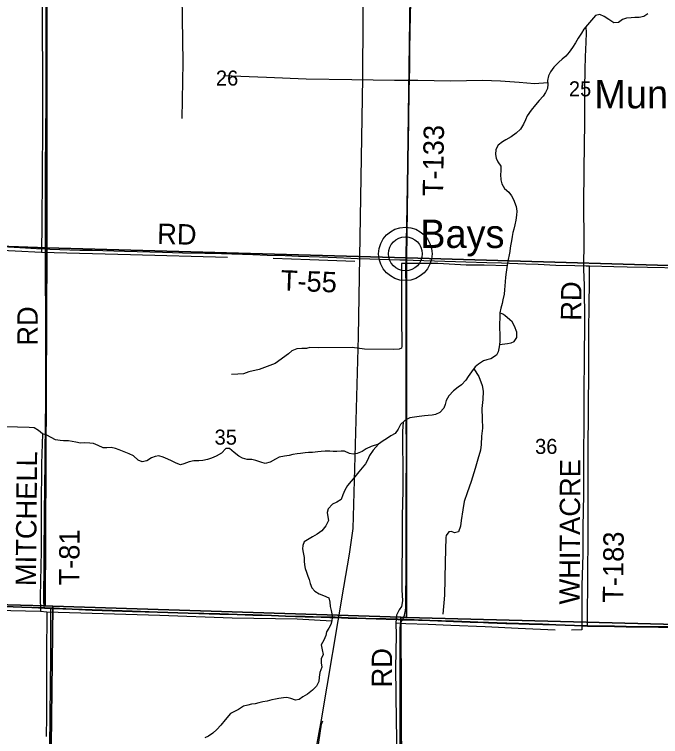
# Model space of a CAD drawing. Extents: x 0 to 39.4, y 0 to 22.
# Drawn here: x 3.277 to 5.077, y 15.083 to 17.096 of the extents above; entities that cross this region are included whole.
import ezdxf

# ---------------------------------------------------------------- set-up
doc = ezdxf.new("R2010")
doc.units = 0
for name, color, linetype in [('GM_X_Interstate_Route', 7, 'Continuous'), ('GM_X_Minor_River', 7, 'Continuous'), ('GM_X_Rail_Line', 7, 'Continuous'), ('GM_X_Section', 7, 'Continuous'), ('GM_X_Section_Text', 7, 'Continuous'), ('GM_X_Township_Road', 7, 'Continuous'), ('GM_X_Township_Road_Text', 7, 'Continuous'), ('GM_X_Unincorporated', 7, 'Continuous'), ('GM_X_Unincorporated_Location', 7, 'Continuous'), ('GM_X_Unincorporated_Text', 7, 'Continuous')]:
    doc.layers.add(name, color=color, linetype=linetype)

msp = doc.modelspace()

# ---------------------------------------------------------------- linework, layer by layer
at = {"layer": 'GM_X_Interstate_Route'}
for points in [[(3.2233, 15.4465), (3.2979, 15.4439), (3.3258, 15.4428), (3.36, 15.4417), (3.3603, 15.4416), (3.378, 15.4408), (3.3848, 15.4405), (3.4376, 15.4384), (3.4935, 15.4361), (3.6053, 15.4322), (3.6752, 15.43), (3.7607, 15.4272), (3.8492, 15.4246), (3.8974, 15.4233), (3.9409, 15.4219), (3.9937, 15.4204), (4.0325, 15.4189), (4.0869, 15.4172), (4.132, 15.4161), (4.1553, 15.4158), (4.1708, 15.4154), (4.1879, 15.4145), (4.2065, 15.4136), (4.2562, 15.4122), (4.3121, 15.4108), (4.3277, 15.4105), (4.3452, 15.4097), (4.358, 15.4092), (4.3696, 15.4088), (4.4348, 15.4066), (4.5, 15.4043), (4.5466, 15.4026), (4.5684, 15.402), (4.5979, 15.4009), (4.646, 15.399), (4.6491, 15.399), (4.6678, 15.3983), (4.6818, 15.398), (4.7113, 15.3969), (4.7486, 15.396), (4.7858, 15.3946), (4.8371, 15.3927), (4.8588, 15.3919), (4.8733, 15.3915), (4.8992, 15.3909), (4.9116, 15.3907), (4.9489, 15.3902), (4.9816, 15.3896), (5.0033, 15.3891), (5.0344, 15.3891), (5.0717, 15.3886), (5.1012, 15.3883)], [(5.1012, 15.3883), (5.0717, 15.3886), (5.0344, 15.3891), (5.0033, 15.3891), (4.9816, 15.3896), (4.9489, 15.3902), (4.9116, 15.3907), (4.8992, 15.3909), (4.8733, 15.3915), (4.8588, 15.3919), (4.8371, 15.3927), (4.7858, 15.3946), (4.7486, 15.396), (4.7113, 15.3969), (4.6818, 15.398), (4.6678, 15.3983), (4.6491, 15.399), (4.646, 15.399), (4.5979, 15.4009), (4.5684, 15.402), (4.5466, 15.4026), (4.5, 15.4043), (4.4348, 15.4066), (4.3696, 15.4088), (4.358, 15.4092), (4.3452, 15.4097), (4.3277, 15.4105), (4.3121, 15.4108), (4.2562, 15.4122), (4.2065, 15.4136), (4.1879, 15.4145), (4.1708, 15.4154), (4.1553, 15.4158), (4.132, 15.4161), (4.0869, 15.4172), (4.0325, 15.4189), (3.9937, 15.4204), (3.9409, 15.4219), (3.8974, 15.4233), (3.8492, 15.4246), (3.7607, 15.4272), (3.6752, 15.43), (3.6053, 15.4322), (3.4935, 15.4361), (3.4376, 15.4384), (3.3848, 15.4405), (3.378, 15.4408), (3.3603, 15.4416), (3.36, 15.4417), (3.3258, 15.4428), (3.2979, 15.4439), (3.2233, 15.4465)]]:
    msp.add_lwpolyline(points, dxfattribs=at)
at = {"layer": 'GM_X_Minor_River'}
for points in [[(3.3608, 17.9054), (3.3547, 17.5399), (3.3559, 17.4483), (3.3544, 17.4248), (3.3541, 17.2022), (3.3551, 16.7839), (3.3531, 16.5126), (3.3521, 16.4325)], [(3.7422, 17.3501), (3.7429, 17.2086), (3.7464, 16.962), (3.7436, 16.8051)], [(5.0417, 17.0976), (5.0303, 17.09), (5.0177, 17.0874), (5.0052, 17.0867), (4.9953, 17.0863), (4.9821, 17.0856), (4.971, 17.0818), (4.96, 17.0731), (4.9471, 17.0724), (4.9327, 17.0812), (4.9202, 17.0903), (4.9081, 17.0953), (4.896, 17.0923), (4.8845, 17.0794), (4.8735, 17.0662), (4.8636, 17.0544), (4.8571, 17.043), (4.848, 17.0294), (4.84, 17.0161), (4.8323, 17.0032), (4.8228, 16.9903), (4.8133, 16.9789), (4.803, 16.971), (4.7935, 16.9627), (4.7802, 16.9487), (4.7703, 16.9358), (4.7649, 16.9244), (4.7626, 16.9119), (4.7633, 16.9012), (4.7626, 16.8894), (4.7564, 16.8777), (4.75, 16.8674), (4.7389, 16.8553), (4.729, 16.8439), (4.7168, 16.8288), (4.7058, 16.8129), (4.7008, 16.8015), (4.6955, 16.7893), (4.6867, 16.7761), (4.6753, 16.7643), (4.6608, 16.7541), (4.6464, 16.7462), (4.6369, 16.7409), (4.6247, 16.7314), (4.6182, 16.7193), (4.6171, 16.7048), (4.6193, 16.6946), (4.6242, 16.6851), (4.6321, 16.6725), (4.6325, 16.6585), (4.6317, 16.649), (4.632, 16.6345), (4.635, 16.6239), (4.6426, 16.6109), (4.6543, 16.6003), (4.6619, 16.59), (4.6675, 16.5801), (4.6751, 16.5603), (4.6765, 16.5474), (4.6754, 16.536), (4.6738, 16.5223), (4.6715, 16.509), (4.6684, 16.4973), (4.6661, 16.4878), (4.6642, 16.4771), (4.6619, 16.4646)], [(4.8688, 17.0606), (4.8704, 17.0445), (4.8688, 17.0187), (4.8675, 16.9773), (4.8659, 16.9419), (4.8654, 16.8888), (4.8655, 16.7942), (4.8639, 16.6654), (4.8629, 16.5617), (4.8634, 16.4686), (4.8627, 16.3858), (4.8645, 16.3398), (4.8649, 16.2384), (4.8646, 16.1335), (4.8636, 16.0461), (4.8634, 15.9645), (4.8623, 15.8611), (4.8624, 15.7574), (4.8606, 15.6666), (4.8611, 15.5906), (4.8578, 15.504), (4.8576, 15.4368), (4.8578, 15.3802), (4.8294, 15.3795)], [(4.7631, 16.9047), (4.7258, 16.9025), (4.6829, 16.906), (4.631, 16.9096), (4.5813, 16.9112), (4.4917, 16.91), (4.4014, 16.911), (4.3358, 16.9116), (4.2174, 16.9135), (4.09, 16.9154), (3.9796, 16.9199), (3.8593, 16.9244)], [(4.6619, 16.4646), (4.6603, 16.4551), (4.6584, 16.4449), (4.6572, 16.435), (4.6557, 16.4251), (4.653, 16.4122), (4.6507, 16.4023), (4.6488, 16.3906), (4.6472, 16.3777), (4.6453, 16.3629), (4.6445, 16.3503), (4.6437, 16.3393), (4.6425, 16.3283), (4.6417, 16.3161), (4.6379, 16.2998), (4.6363, 16.2899), (4.6321, 16.2767), (4.629, 16.2637), (4.6289, 16.2197), (4.6292, 16.2064), (4.6292, 16.1931), (4.6295, 16.1828), (4.628, 16.1691), (4.6245, 16.1555), (4.6199, 16.1456), (4.6044, 16.1358), (4.5933, 16.1328), (4.5839, 16.1298), (4.5702, 16.1211), (4.5603, 16.1131), (4.5508, 16.0991), (4.5412, 16.0862), (4.5351, 16.0767), (4.523, 16.0635), (4.5131, 16.0563), (4.5005, 16.0464), (4.4876, 16.0328), (4.4799, 16.0195), (4.4769, 16.0081), (4.4734, 15.9986), (4.462, 15.9861), (4.4506, 15.9809), (4.4411, 15.979), (4.4294, 15.9779), (4.4191, 15.9764), (4.4047, 15.9749), (4.3918, 15.9734), (4.3785, 15.9708), (4.3644, 15.9636), (4.3527, 15.953), (4.3465, 15.9394), (4.3378, 15.9276), (4.3256, 15.9208), (4.3135, 15.9125), (4.304, 15.9072), (4.291, 15.8974), (4.2769, 15.8807), (4.2666, 15.8663), (4.2605, 15.853), (4.2552, 15.8431), (4.2457, 15.8318), (4.2362, 15.8212), (4.2251, 15.8071), (4.2156, 15.795), (4.2049, 15.7825), (4.1973, 15.7692), (4.192, 15.7567), (4.1874, 15.7438), (4.1756, 15.7366), (4.1634, 15.7302), (4.1509, 15.7177), (4.1482, 15.7075), (4.15, 15.6949), (4.1519, 15.6847), (4.1443, 15.6699), (4.1336, 15.6566), (4.1207, 15.6471), (4.1074, 15.6392), (4.0979, 15.6343), (4.0846, 15.6256), (4.0808, 15.6153), (4.08, 15.6058), (4.0815, 15.5963), (4.0841, 15.5819), (4.084, 15.572), (4.0851, 15.5614), (4.087, 15.5511), (4.0904, 15.5409), (4.0949, 15.5298), (4.0983, 15.5203), (4.1013, 15.5097), (4.1058, 15.4975), (4.1138, 15.488), (4.1263, 15.4807), (4.1384, 15.4757), (4.1528, 15.47), (4.1554, 15.4575), (4.1569, 15.4457), (4.1599, 15.4347), (4.1618, 15.4248), (4.1621, 15.4149)], [(3.8703, 16.4183), (3.6006, 16.426), (3.3521, 16.4325), (2.911, 16.4544)], [(4.2258, 16.4074), (4.1002, 16.4116), (3.9978, 16.4153)], [(4.6494, 16.3945), (4.5862, 16.3965), (4.5353, 16.3966), (4.4564, 16.4014), (4.3559, 16.4017), (4.3553, 16.3303), (4.3551, 16.2516), (4.356, 16.1707), (4.3552, 16.1658), (4.3491, 16.1624), (4.3339, 16.1613), (4.2527, 16.163), (4.2178, 16.1673), (4.1253, 16.1668), (4.1002, 16.1677), (4.0904, 16.1647), (4.0778, 16.1643), (4.0642, 16.164), (4.0497, 16.1579), (4.041, 16.15), (4.0034, 16.1231), (3.9593, 16.1058), (3.9301, 16.099), (3.9153, 16.0941), (3.8993, 16.0934), (3.8815, 16.0916)], [(4.6287, 16.1758), (4.6508, 16.1786), (4.6614, 16.1801), (4.669, 16.1842), (4.6766, 16.1948), (4.6767, 16.2097), (4.6703, 16.2268), (4.6635, 16.2386), (4.6574, 16.2447), (4.6438, 16.2561), (4.6375, 16.2604), (4.629, 16.2637)], [(4.557, 16.1082), (4.5712, 16.0865), (4.5799, 16.0614), (4.5828, 16.0454), (4.5816, 16.0226), (4.5797, 15.9972), (4.58, 15.9683), (4.5814, 15.9421), (4.5787, 15.9201), (4.5775, 15.8969), (4.5759, 15.8813), (4.5682, 15.8559), (4.561, 15.8305), (4.5491, 15.7937), (4.5387, 15.7622), (4.5303, 15.7379), (4.5268, 15.7151), (4.5214, 15.6851), (4.5195, 15.6695), (4.5145, 15.6532), (4.5031, 15.6509), (4.4944, 15.6548), (4.4872, 15.6533), (4.4803, 15.6434), (4.4788, 15.6377), (4.4775, 15.569), (4.4749, 15.4774), (4.471, 15.4242)], [(3.3184, 15.9444), (2.9641, 15.9546), (2.7396, 15.961), (2.5446, 15.965), (2.3674, 15.9701)], [(4.291, 15.8974), (4.2705, 15.8916), (4.2568, 15.8853), (4.2458, 15.877), (4.2321, 15.8721), (4.2211, 15.8698), (4.2105, 15.8714), (4.1969, 15.8783), (4.187, 15.8787), (4.1756, 15.8776), (4.165, 15.8772), (4.1555, 15.8784), (4.1426, 15.8788), (4.132, 15.8773), (4.1225, 15.8766), (4.1073, 15.8747), (4.0963, 15.8744), (4.0868, 15.8737), (4.0739, 15.8718), (4.0644, 15.8707), (4.0523, 15.8688), (4.0428, 15.8662), (4.0299, 15.8643), (4.0147, 15.8617), (4.0045, 15.8557), (3.9893, 15.8474), (3.9756, 15.844), (3.9631, 15.8478), (3.9494, 15.8528), (3.9381, 15.8547), (3.9259, 15.8548), (3.9127, 15.8586), (3.902, 15.8643), (3.8888, 15.8746), (3.8759, 15.8861), (3.8657, 15.8861), (3.8543, 15.8728), (3.8395, 15.8645), (3.8262, 15.8593), (3.8151, 15.8551), (3.8022, 15.8525), (3.7905, 15.8518), (3.7772, 15.851), (3.7639, 15.8484), (3.7491, 15.8428), (3.7396, 15.8405), (3.7275, 15.8447), (3.715, 15.8512), (3.704, 15.8558), (3.6911, 15.862), (3.6797, 15.865), (3.6691, 15.8635), (3.6592, 15.8602), (3.6459, 15.8518), (3.633, 15.8485), (3.622, 15.8534), (3.6088, 15.8649), (3.5963, 15.871), (3.5827, 15.8763), (3.5686, 15.8817), (3.5588, 15.8859), (3.5466, 15.8886), (3.5345, 15.8875), (3.5239, 15.8875), (3.5099, 15.8937), (3.4977, 15.8994), (3.4867, 15.9006), (3.4731, 15.9014), (3.4609, 15.901), (3.4481, 15.903), (3.4378, 15.9053), (3.4272, 15.9072), (3.4139, 15.9076), (3.4044, 15.9084), (3.3916, 15.9096), (3.3791, 15.9165), (3.3677, 15.9234), (3.3548, 15.9268), (3.3438, 15.9364), (3.3316, 15.9431), (3.3184, 15.9444)], [(4.36, 15.9597), (4.3587, 15.9333), (4.3578, 15.8934), (4.3595, 15.8371), (4.3593, 15.7691), (4.3576, 15.697), (4.3577, 15.6172), (4.3564, 15.5442), (4.3566, 15.4914), (4.358, 15.4614), (4.3557, 15.4458), (4.3492, 15.4364), (4.3416, 15.4208), (4.3396, 15.4003), (4.3403, 15.3657), (4.3392, 15.2749), (4.3407, 15.1266)], [(3.3548, 15.9268), (3.3523, 15.8429), (3.3511, 15.7187), (3.3516, 15.6005), (3.3485, 15.4721), (3.3492, 15.4322)], [(2.3674, 15.4606), (2.6034, 15.4542), (2.8693, 15.4478), (3.0996, 15.4379), (3.3492, 15.4322), (3.367, 15.4306), (3.6822, 15.4209), (3.8833, 15.4138), (4.0646, 15.411), (4.1609, 15.4054)], [(3.367, 15.4306), (3.3659, 15.3076), (3.3661, 15.1389)], [(4.1621, 15.4149), (4.1609, 15.4054), (4.1586, 15.3951), (4.1529, 15.3853), (4.1464, 15.3747), (4.1449, 15.3648), (4.1392, 15.3519), (4.1315, 15.3386), (4.1345, 15.3249), (4.1371, 15.3116), (4.1318, 15.2991), (4.1314, 15.2881), (4.1332, 15.2763), (4.1279, 15.2615), (4.1256, 15.2486), (4.1255, 15.2364), (4.1183, 15.2236), (4.1072, 15.2122), (4.0932, 15.2008), (4.081, 15.1933), (4.0704, 15.1865), (4.0605, 15.1846), (4.0469, 15.1892), (4.0362, 15.1915), (4.0264, 15.1904), (4.0138, 15.1893), (4.0044, 15.1874), (3.9945, 15.1852), (3.9808, 15.1818), (3.9694, 15.1799), (3.958, 15.1765), (3.9474, 15.1743), (3.9372, 15.1728), (3.9273, 15.1706), (3.9151, 15.1672), (3.9015, 15.1581), (3.8904, 15.1528), (3.8794, 15.1472), (3.864, 15.1292)], [(4.3396, 15.4003), (4.3677, 15.3983), (4.4295, 15.3966), (4.4932, 15.393), (4.5881, 15.3893), (4.6803, 15.3853), (4.7838, 15.38)], [(3.3661, 15.1389), (3.3652, 15.0829)], [(3.864, 15.1292), (3.8518, 15.1144), (3.8408, 15.1023), (3.8294, 15.0924), (3.8173, 15.084), (3.8078, 15.0795)], [(4.1121, 14.5272), (4.1125, 14.6746), (4.1113, 14.8514), (4.1132, 14.9612), (4.1186, 15.0167), (4.125, 15.0676), (4.133, 15.117), (4.136, 15.1265)], [(4.3407, 15.1266), (4.3454, 14.8897), (4.3451, 14.5686), (4.3451, 14.5043), (4.3705, 14.48), (4.3697, 14.3451), (4.3703, 14.1)]]:
    msp.add_lwpolyline(points, dxfattribs=at)
at = {"layer": 'GM_X_Rail_Line'}
msp.add_lwpolyline([(4.9299, 20.9), (4.9207, 20.2492), (4.9136, 19.4102), (4.7206, 18.8553), (4.6861, 18.7801), (4.66, 18.7382), (4.6327, 18.7007), (4.4144, 18.4874), (4.369, 18.4419), (4.3263, 18.3862), (4.2933, 18.3287), (4.2793, 18.2799), (4.2724, 18.2363), (4.2649, 18.1427), (4.2497, 17.419), (4.2467, 16.9177), (4.235, 16.198), (4.2196, 15.6628), (4.2092, 15.5913), (4.1936, 15.4989), (4.1313, 15.1291), (4.1146, 15.0383)], dxfattribs=at)
at = {"layer": 'GM_X_Section'}
for points in [[(2.3633, 17.4784), (3.367, 17.4429), (3.3671, 16.4448), (2.3619, 16.4807)], [(3.367, 17.4429), (4.3832, 17.4133), (4.3694, 16.4169), (3.3671, 16.4448)], [(4.3832, 17.4133), (5.3882, 17.3864), (5.386, 16.3879), (4.3694, 16.4169)], [(2.3619, 16.4807), (3.3671, 16.4448), (3.3623, 15.4472), (2.3597, 15.4744), (2.3594, 15.5066)], [(3.3671, 16.4448), (4.3694, 16.4169), (4.3695, 15.415), (4.3536, 15.4159), (3.3836, 15.4465), (3.3623, 15.4472)], [(4.3694, 16.4169), (5.386, 16.3879), (5.3717, 15.3889), (4.3695, 15.415)], [(2.3597, 15.4744), (3.3623, 15.4472), (3.3836, 15.4465), (3.3725, 14.5132), (2.3556, 14.5215)], [(3.3836, 15.4465), (4.3536, 15.4159), (4.3571, 14.4954), (3.3725, 14.5132)], [(4.3536, 15.4159), (4.3695, 15.415), (5.3717, 15.3889), (5.3657, 14.4352), (4.3571, 14.4954)]]:
    msp.add_lwpolyline(points, close=True, dxfattribs=at)
at = {"layer": 'GM_X_Township_Road'}
msp.add_line((3.3605, 15.4411), (3.3782, 15.4403), dxfattribs=at)
for points in [[(3.3636, 16.4419), (3.3636, 16.4491), (3.3634, 16.4833), (3.3634, 16.5299), (3.3633, 16.5952), (3.364, 16.6543), (3.3647, 16.7724), (3.365, 16.8408), (3.3651, 17.0398), (3.365, 17.13), (3.365, 17.1953), (3.3654, 17.2357), (3.3663, 17.2948), (3.3667, 17.3414), (3.3668, 17.416), (3.3669, 17.4424)], [(4.368, 16.4116), (4.3682, 16.4289), (4.3692, 16.4693), (4.3699, 16.5034), (4.3712, 16.5687), (4.3721, 16.6122), (4.3733, 16.6744), (4.3746, 16.7365), (4.3759, 16.8049), (4.3771, 16.8795), (4.378, 16.9168), (4.3783, 16.9448), (4.379, 16.9945), (4.3799, 17.0504), (4.3826, 17.1716), (4.3834, 17.1996), (4.3843, 17.2369), (4.3855, 17.2928), (4.3863, 17.3301), (4.387, 17.3611), (4.3877, 17.3953), (4.3879, 17.4129)], [(2.3644, 16.48), (2.3849, 16.4793), (2.4626, 16.4782), (2.4936, 16.4771), (2.5278, 16.4763), (2.5931, 16.4749), (2.6521, 16.4741), (2.708, 16.473), (2.7422, 16.472), (2.8292, 16.469), (2.9596, 16.4636), (3.0373, 16.4602), (3.0776, 16.4579), (3.1149, 16.4557), (3.1738, 16.4524), (3.2111, 16.4505), (3.2762, 16.4467), (3.3383, 16.4429), (3.3636, 16.4419)], [(3.3605, 15.4411), (3.36, 15.448), (3.3593, 15.4573), (3.359, 15.4697), (3.3596, 15.563), (3.3596, 15.5941), (3.3607, 15.6967), (3.3617, 15.7869), (3.3623, 15.8397), (3.3626, 15.8832), (3.3638, 15.9423), (3.3641, 16.0231), (3.3642, 16.0605), (3.3641, 16.0915), (3.3643, 16.1289), (3.3642, 16.1662), (3.3643, 16.2128), (3.3641, 16.2688), (3.3634, 16.3527), (3.3633, 16.39), (3.3634, 16.4273), (3.3636, 16.4419)], [(3.3636, 16.4419), (3.3755, 16.4414), (3.4594, 16.4389), (3.4936, 16.4382), (3.5837, 16.4356), (3.6894, 16.4332), (3.7453, 16.4313), (3.8074, 16.43), (3.854, 16.429), (3.941, 16.4264), (3.9814, 16.4248), (4.0311, 16.4235), (4.0684, 16.4219), (4.1274, 16.42), (4.174, 16.4181), (4.2143, 16.4161), (4.233, 16.4152), (4.2671, 16.4143), (4.3199, 16.4124), (4.351, 16.4117), (4.368, 16.4116)], [(4.3582, 15.4087), (4.3612, 15.4144), (4.3638, 15.4211), (4.3652, 15.427), (4.3665, 15.4343), (4.3673, 15.4436), (4.3678, 15.4621), (4.368, 15.5461), (4.3684, 15.6642), (4.3686, 15.7139), (4.3689, 15.7948), (4.3692, 15.8414), (4.3691, 15.9004), (4.3688, 15.9502), (4.3689, 15.9937), (4.3686, 16.0279), (4.3687, 16.1398), (4.3684, 16.1989), (4.3683, 16.2268), (4.3681, 16.2735), (4.368, 16.3263), (4.3678, 16.3947), (4.368, 16.4116)], [(4.368, 16.4116), (4.3696, 16.4115), (4.3883, 16.411), (4.4473, 16.4086), (4.5343, 16.4058), (4.5933, 16.4043), (4.6337, 16.4033), (4.702, 16.4002), (4.736, 16.3991), (4.7857, 16.3972), (4.8385, 16.3955), (4.8696, 16.3947), (4.8795, 16.3945)], [(4.8735, 15.391), (4.8736, 15.3938), (4.8736, 15.4026), (4.8746, 15.5323), (4.8749, 15.5634), (4.8752, 15.61), (4.8756, 15.6566), (4.8754, 15.7872), (4.8757, 15.8525), (4.8757, 15.8867), (4.8763, 15.9862), (4.8769, 16.0328), (4.877, 16.067), (4.8771, 16.1198), (4.8777, 16.2069), (4.8782, 16.2908), (4.8789, 16.3437), (4.8793, 16.3748), (4.8796, 16.3872), (4.8795, 16.3903), (4.8795, 16.3945)], [(4.8795, 16.3945), (4.9473, 16.3933), (4.9846, 16.3922), (5.0405, 16.3914), (5.1369, 16.3896), (5.199, 16.3881), (5.2612, 16.3869), (5.3388, 16.3849), (5.3663, 16.3841), (5.3692, 16.3841), (5.3728, 16.3843), (5.3783, 16.3847)], [(2.3625, 15.4768), (2.3693, 15.4766), (2.4237, 15.4742), (2.5433, 15.4704), (2.6008, 15.4687), (2.666, 15.4666), (2.7561, 15.4638), (2.854, 15.4603), (2.8974, 15.4588), (2.9797, 15.4552), (3.0512, 15.4523), (3.118, 15.4498), (3.1614, 15.4479), (3.2236, 15.4459), (3.2981, 15.4434), (3.3261, 15.4423), (3.3605, 15.4411)], [(3.3732, 14.5144), (3.373, 14.5663), (3.3734, 14.644), (3.374, 14.7746), (3.3743, 14.871), (3.3746, 14.9083), (3.3748, 14.9611), (3.3765, 15.1414), (3.378, 15.3062), (3.3781, 15.3652), (3.3782, 15.4336), (3.3782, 15.4403)], [(3.3782, 15.4403), (3.385, 15.4399), (3.4378, 15.4379), (3.4937, 15.4355), (3.6056, 15.4317), (3.6755, 15.4294), (3.7609, 15.4267), (3.8494, 15.424), (3.8976, 15.4228), (3.9411, 15.4214), (3.9939, 15.4199), (4.0328, 15.4184), (4.0871, 15.4166), (4.1322, 15.4155), (4.1555, 15.4152), (4.171, 15.4148), (4.1881, 15.4139), (4.2067, 15.4131), (4.2564, 15.4117), (4.3124, 15.4103), (4.3279, 15.4099), (4.3454, 15.4092), (4.3582, 15.4087)], [(4.3528, 14.4954), (4.3532, 14.5012), (4.3534, 14.517), (4.3537, 14.5605), (4.3531, 14.6942), (4.3525, 14.8962), (4.3523, 14.9584), (4.3517, 15.1262), (4.3517, 15.2537), (4.3515, 15.3656), (4.3518, 15.3842), (4.3528, 15.3947), (4.3537, 15.3991), (4.3549, 15.4028), (4.3582, 15.4087)], [(4.3582, 15.4087), (4.3698, 15.4083), (4.435, 15.406), (4.5003, 15.4038), (4.5469, 15.4021), (4.5686, 15.4014), (4.5981, 15.4003), (4.6463, 15.3984), (4.6494, 15.3984), (4.668, 15.3978), (4.682, 15.3975), (4.7115, 15.3963), (4.7488, 15.3955), (4.7861, 15.394), (4.8373, 15.3921), (4.8591, 15.3914), (4.8735, 15.391)], [(4.8735, 15.391), (4.8994, 15.3903), (4.9119, 15.3902), (4.9492, 15.3897), (4.9818, 15.3891), (5.0035, 15.3885), (5.0346, 15.3885), (5.0719, 15.3881), (5.1014, 15.3877), (5.1325, 15.3874), (5.1589, 15.387), (5.1978, 15.3866), (5.2133, 15.3864), (5.2304, 15.3863), (5.2723, 15.3854), (5.3236, 15.3847), (5.3427, 15.3846), (5.366, 15.3846)]]:
    msp.add_lwpolyline(points, dxfattribs=at)
at = {"layer": 'GM_X_Unincorporated'}
for radius in [0.0744, 0.0472]:
    msp.add_circle((4.3662, 16.4283), radius, dxfattribs=at)
at = {"layer": 'GM_X_Unincorporated_Location'}
msp.add_line((4.3662, 16.4283), (4.3662, 16.4283), dxfattribs=at)

# ---------------------------------------------------------------- texts
at = {"layer": 'GM_X_Section_Text'}
for s, p in [('26', (3.8384, 16.8973)), ('25', (4.8218, 16.8673)), ('35', (3.8347, 15.8965)), ('36', (4.7276, 15.8707))]:
    msp.add_text(s, height=0.04186, rotation=0, dxfattribs=at).set_placement(p)
at = {"layer": 'GM_X_Township_Road_Text'}
for s, rotation, p in [('T-133', 89.1582, (4.4712, 16.5887)), ('RD', 358.538, (3.6741, 16.4562)), ('T-55', 357.8789, (4.0183, 16.3263)), ('RD', 89.5063, (4.8561, 16.2416)), ('RD', 90, (3.3419, 16.1723)), ('MITCHELL', 89.4587, (3.3369, 15.5021)), ('WHITACRE', 89.7407, (4.8519, 15.4508)), ('T-81', 89.6545, (3.4579, 15.5038)), ('T-183', 89.4382, (4.9729, 15.4556)), ('RD', 90, (4.3294, 15.2198))]:
    msp.add_text(s, height=0.05682, rotation=rotation, dxfattribs=at).set_placement(p)
at = {"layer": 'GM_X_Unincorporated_Text'}
for s, p in [('Mungen', (4.8926, 16.8339)), ('Bays', (4.4076, 16.4447))]:
    msp.add_text(s, height=0.07898, rotation=0, dxfattribs=at).set_placement(p)

doc.saveas('drawing.dxf')
